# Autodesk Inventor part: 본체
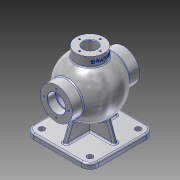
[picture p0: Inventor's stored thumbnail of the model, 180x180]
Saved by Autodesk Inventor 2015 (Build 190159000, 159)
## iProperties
Created: 2025-08
Part Number: 본체
Material: 알루미늄 6061
Document SubType Name: Modeling
Designer: USER
Density: 2.7 g/cm^3
Appearance: 알루미늄 - 평지
Mass: 1526.21 g
Surface Area: 1175.8 cm^2
Volume: 565.262 cm^3
Author: USER
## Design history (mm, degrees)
sketch "스케치1"
  geometry: L1 (-62.5, 62.5)-(62.5, 62.5); L2 (62.5, 62.5)-(62.5, -62.5); L3 (62.5, -62.5)-(-62.5, -62.5); L4 (-62.5, -62.5)-(-62.5, 62.5); L5 (-62.5, 62.5)-(62.5, -62.5); L6 (62.5, 62.5)-(-62.5, -62.5); 1 further point
  constraints: 12 end point, 2 midpoint, 2 parallel, 1 horizontal, 1 perpendicular
  dimensions: "d0" = 125 distance of L2.end L3.end; "d1" = 125 distance of L1.end L2.end
extrude "돌출1" new body sketch "스케치1" distance "d2" = 10; taper "d3" = 0 deg
sketch "스케치2"
  geometry: L1 (0, 139)-(0, 130); L2 (0, 130)-(0, 31); L3 (62.5, 10)-(62.5, 0) reference; L4 (62.5, 0)-(-62.5, 0) reference; L5 (-62.5, 0)-(-62.5, 10) reference; L6 (-62.5, 10)-(62.5, 10) reference; A1 r 54 centre (0, 85) between (0, 139) and (0, 31); 2 further points
  constraints: 4 end point, 2 point on circle, 2 point on line, 1 centre point, 1 midpoint, 1 vertical, 1 vertical alignment
  dimensions: "d4" = 108 diameter of A1; "d5" = 85 distance from line of A1.centre L4
revolve "회전1" sketch "스케치2" stored, may be unused: angle "d6" = 90 deg
sketch "스케치3"
  geometry: L1 (62.5, 62.5)-(62.5, -62.5) reference; L2 (62.5, -62.5)-(-62.5, -62.5) reference; L3 (-62.5, -62.5)-(-62.5, 62.5) reference; L4 (-62.5, 62.5)-(62.5, 62.5) reference; L5 (-4, 50.5)-(4, 50.5); L6 (4, 50.5)-(4, -50.5); L7 (4, -50.5)-(-4, -50.5); L8 (-4, -50.5)-(-4, 50.5); L9 (-50.5, 4)-(50.5, 4); L10 (50.5, 4)-(50.5, -4); L11 (50.5, -4)-(-50.5, -4); L12 (-50.5, -4)-(-50.5, 4); 1 further point
  constraints: 16 end point, 4 parallel, 2 horizontal, 2 perpendicular
  dimensions: "d7" = 8 distance of L5.end L5.start; "d8" = 12 distance between parallel lines of L5 L4; "d9" = 12 distance between parallel lines of L2 L7; "d10" = 4 distance from line of L8 point (0, 0); "d11" = 8 distance of L11.end L9.start; "d12" = 12 distance between parallel lines of L12 L3; "d13" = 12 distance between parallel lines of L1 L10; "d14" = 4 distance from line of point (0, 0) L9
extrude "돌출2" join sketch "스케치3" stored distance "d15" = 10; taper "d16" = 0 deg
feature "면 기울기1" dims angle "d17" = 20 deg
feature "면 기울기2" dims angle "d18" = 20 deg
feature "면 기울기3" dims angle "d19" = 20 deg
feature "면 기울기4" dims angle "d20" = 20 deg
node "작업 평면1"
sketch "스케치4"
  geometry: C1 r 27 at (0, 0); 1 further point
  constraints: 1 centre point, 1 coincident
  dimensions: "d22" = 54 diameter of C1
extrude "돌출3" join sketch "스케치4" stored distance "d23" = 10; taper "d24" = 0 deg
node "작업 평면2"
sketch "스케치5"
  geometry: C1 r 31 at (0, 85); 1 further point
  constraints: 1 centre point, 1 vertical alignment
  dimensions: "d26" = 62 diameter of C1; "d27" = 85 distance of C1.centre point (0, 0)
extrude "돌출4" join sketch "스케치5" distance "d28" = 130; taper "d29" = 0 deg
sketch "스케치6"
  geometry: L1 (62.5, 0)-(-62.5, 0) reference; L2 (-62.5, 0)-(-62.5, 10) reference; L3 (-62.5, 10)-(-50.5, 10) reference; L4 (-50.5, 10)-(-37.385, 46.034) reference; L5 (-27, 131.765)-(-27, 150) reference; L6 (-27, 150)-(27, 150) reference; L7 (27, 150)-(27, 131.765) reference; L8 (37.385, 46.034)-(50.5, 10) reference; L9 (50.5, 10)-(62.5, 10) reference; L10 (62.5, 10)-(62.5, 0) reference; L11 (0, 129)-(0, 41); A1 r 54 centre (0, 85) between (-27, 131.765) and (-37.385, 46.034) reference; A2 r 54 centre (0, 85) between (37.385, 46.034) and (27, 131.765) reference; A3 r 44 centre (0, 85) between (0, 129) and (0, 41); 1 further point
  constraints: 2 end point, 2 point on circle, 1 centre point, 1 coincident, 1 vertical
  dimensions: "d30" = 88 diameter of A3
revolve "회전2" sketch "스케치6" stored, may be unused: angle "d31" = 360 deg
sketch "스케치7"
  geometry: 1 further point
fillet "모깎기1" dims "d33" = 16
fillet "모깎기2" dims "d34" = 16
sketch "스케치9"
  geometry: 1 further point
hole "구멍1" diameter "d37" = 11; stored, may be unused: countersink angle "d41" = 90 deg, drill point angle "d43" = 0 deg; dims "d38" = 6, "d39" = 4, "d40" = 2, "d42" = 8, "d116" = 10, "d117" = 10
hole "구멍2" diameter "d51" = 30; stored, may be unused: countersink angle "d55" = 90 deg, drill point angle "d57" = 0 deg; dims "d49" = 10, "d50" = 10, "d52" = 6, "d53" = 4, "d54" = 2, "d56" = 8
sketch "스케치11"
  geometry: L1 (0, 0)-(0, 24); 1 further point
  constraints: 2 end point, 1 vertical
  dimensions: "d58" = 24 distance of L1.start L1.end
hole "구멍3" sketch "스케치11" at (0, 24) diameter "d59" = 3.242; stored, may be unused: countersink angle "d63" = 90 deg, drill point angle "d65" = 118 deg; dims "d60" = 12, "d61" = 4, "d62" = 2, "d64" = 15
hole "구멍4" diameter "d68" = 26; stored, may be unused: countersink angle "d72" = 90 deg, drill point angle "d74" = 0 deg; dims "d66" = 10, "d67" = 10, "d69" = 8, "d70" = 4, "d71" = 2, "d73" = 100
sketch "스케치12"
  geometry: 1 further point
sketch "스케치14"
  geometry: C1 r 17.5 at (0, 0); 1 further point
  constraints: 1 centre point
  dimensions: "d78" = 35 diameter of C1
extrude "돌출5" cut sketch "스케치14" distance "d79" = 16; taper "d80" = 0 deg
sketch "스케치15"
  geometry: C1 r 17.5 at (0, 0); 1 further point
  constraints: 1 centre point
  dimensions: "d81" = 35 diameter of C1
extrude "돌출6" cut sketch "스케치15" distance "d82" = 16; taper "d83" = 0 deg
sketch "스케치16"
  geometry: L1 (0, 0)-(0, 20)
  constraints: 2 end point, 1 vertical
  dimensions: "d84" = 20 distance of L1.start L1.end
hole "구멍5" sketch "스케치16" at (0, 20) diameter "d85" = 3.242; stored, may be unused: countersink angle "d89" = 90 deg, drill point angle "d91" = 118 deg; dims "d86" = 9, "d87" = 4, "d88" = 2, "d90" = 11
fillet "모깎기3" dims "d95" = 3
fillet "모깎기4" dims "d96" = 3
fillet "모깎기5" dims "d97" = 3
fillet "모깎기6" dims "d98" = 3
fillet "모깎기7" dims "d99" = 3
sketch "스케치17"
  geometry: L1 (-13, 150)-(13, 150) reference; 2 further points
  constraints: 1 vertical alignment, 1 other
  dimensions: "d102" = 9 distance from line of point (0, 141) L1
feature "엠보싱2" sketch "스케치17" dims "d103" = 0.5, "d104" = 0
chamfer "모따기1" distance "d105" = 0.6; stored, may be unused: second distance "d106" = 2, angle "d107" = 45 deg
sketch "스케치18"
  geometry: 1 further point
chamfer "모따기2" distance "d108" = 0.6; stored, may be unused: second distance "d109" = 2, angle "d110" = 45 deg
chamfer "모따기3" distance "d111" = 1; stored, may be unused: second distance "d112" = 2, angle "d113" = 45 deg
sketch "스케치19"
  geometry: 1 further point
node "솔리드1"
pattern_linear "직사각형 패턴1" dims "d48" = 93
mirror "대칭1"
pattern_circular "원형 패턴1" dims angle "d76" = 360 deg
mirror "대칭2"
pattern_circular "원형 패턴2" dims angle "d93" = 360 deg
node "절단 모서리 투영1"
node "절단 모서리 투영2"
node "절단 모서리 투영3"
other parameters: "d25" = -65
